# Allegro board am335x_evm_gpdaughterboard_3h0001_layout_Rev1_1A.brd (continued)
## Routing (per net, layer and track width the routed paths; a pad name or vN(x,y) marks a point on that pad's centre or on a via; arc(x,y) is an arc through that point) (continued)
AM335X_XDMA_EVENT_INTR1: length 72.8
  TOP w0.121: v2(104.33,78.13) U43.A15
  LY3 w0.102: 104.59,94.21 104.59,98.21 105.57,99.2 105.57,102.4 104.97,103.01 ; v2(104.33,78.13) 104.33,78.65
  LY3 w0.121: 104.59,94.21 104.59,78.9 104.33,78.65 104.33,78.65 ; 104.97,103.01 104.59,103.39 v1(104.59,118.3)
  LY6 w0.102: 104.09,78.65 104.09,78.37 v2(104.33,78.13)
  LY6 w0.121: v1(110.72,131.95) 111.49,131.19 111.49,119.76 110.03,118.3 v1(104.59,118.3) ; 104.09,78.65 104.09,79.11 v1(103.42,79.79)
  BOTTOM w0.121: v1(110.72,131.95) 110.72,138.66 J3.32 ; R158.2 v1(103.42,79.79)
AUD_BCLK: length 119
  TOP w0.121: v1(106.2,91.97) v1(102.8,91.97) ; v2(104.33,74.12) U43.E15 ; v1(60.74,145.07) 61.16,145.49 U51.38
  LY3 w0.102: v2(104.33,74.12) 104.33,74.54 104.73,74.94 104.73,76.12 105.13,76.52 105.31,76.52 105.94,77.15 105.94,78.52 106.08,78.65
  LY3 w0.121: v1(60.74,145.07) 60.11,144.44 60.11,114.54 v1(60.53,114.12) ; v1(102.8,91.97) 102.8,93.13 102.65,93.28 102.65,98.97 103.03,99.35 103.42,99.35 103.67,99.61 103.67,102.53 103.51,102.68 103.51,109.45 103.21,109.75 v1(103.21,110.19) ; 106.08,78.65 106.2,78.78 v1(106.2,91.97)
  LY6 w0.121: v1(60.53,114.12) 61.68,114.12 62.24,113.56 99.84,113.56 v1(103.21,110.19)
AUD_DIN: length 136.6
  TOP w0.121: v1(62.27,144.06) 62.16,144.16 U51.40 ; v2(104.33,73.12) U43.F15 ; v1(64.99,115.15) 65.16,114.98 98.47,114.98 98.74,114.71 102.15,114.71 105.04,117.6 v1(105.04,118.75)
  LY3 w0.102: v2(104.33,73.12) 104.33,72.71 104.93,72.11 104.93,71.96 105.38,71.52 107.6,71.52 107.86,71.26
  LY3 w0.121: 107.86,71.26 108.02,71.1 110.22,71.1 110.85,71.72 110.85,74.65 111.29,75.09 111.29,82.08 110.58,82.79 110.58,82.81 110.32,83.07 110.32,83.44 110.57,83.69 110.57,107.85 111.01,108.3 111.6,108.3 111.92,108.62 111.92,114.46 109.82,116.55 107.24,116.55 v1(105.04,118.75) ; v1(64.99,115.15) 64.99,134.07 62.16,136.9 62.16,143.95 v1(62.27,144.06)
AUD_DOUT: length 168.9
  TOP w0.121: U51.41 v1(62.66,145.08) ; v2(103.33,73.12) U43.F14
  LY6 w0.102: v2(103.33,73.12) 103.78,73.12 104.17,73.52 104.69,73.52 104.9,73.73 106.5,73.73 106.73,73.96 106.73,74.12 107.13,74.52 107.72,74.52 107.73,74.51 107.73,74.51 107.86,74.51
  LY6 w0.121: 107.86,74.51 108.97,74.51 111.26,76.8 111.26,79.41 113.29,81.44 123.06,81.44 127.44,85.82 127.44,147.87 118.24,157.06 81.44,157.06 77.44,153.06 77.44,152.38 71.22,146.15 63.73,146.15 v1(62.66,145.08)
AUD_FSX: length 112.7
  TOP w0.121: U51.39 v1(61.66,145.1) ; v2(102.33,73.12) U43.F13
  LY3 w0.121: v1(59.85,101.38) 61.18,102.71 61.18,115.29 60.74,115.73 60.74,144.18 v1(61.66,145.1)
  LY6 w0.102: 96.73,78.65 96.73,75.92 96.33,75.52 96.14,75.52 95.94,75.32 95.94,71.93 96.14,71.73 101.53,71.73 101.73,71.93 101.73,72.52 v2(102.33,73.12)
  LY6 w0.121: 96.73,78.65 96.73,78.9 94.09,81.54 94.09,84.49 92.72,85.87 75.66,85.87 74.26,87.26 74.26,92.87 66.33,100.81 60.43,100.81 v1(59.85,101.38)
AUD_HPLOUT: length 31.9
  TOP w0.279: U51.18 v1(63.66,154.21)
  TOP w0.381: C198.1 v1(41.39,145.63)
  BOTTOM w0.381: v1(63.66,154.21) 62.77,155.1 54.14,155.1 50.84,151.8 50.84,147.06 49.25,145.48 41.54,145.48 v1(41.39,145.63)
AUD_HPLOUT_JCK: length 12.8
  TOP w0.381: J26.2 32.52,156.02 34.2,154.34 38.39,154.34 39.92,152.82 C198.2
AUD_HPOUTCABLEDET: length 0.7
  TOP w0.121: v2(103.33,68.13) U43.K14
AUD_HPROUT: length 35.4
  TOP w0.279: v1(61.38,154.22) 61.16,154 U51.23
  TOP w0.381: v1(35.67,145.63) C197.1
  BOTTOM w0.381: v1(61.38,154.22) 61,154.6 54.39,154.6 51.47,151.68 51.47,146.98 49.47,144.97 41.24,144.97 40.73,145.48 36.5,145.48 36.35,145.63 v1(35.67,145.63)
AUD_HPROUT_JCK: length 27.2
  TOP w0.381: C197.2 31.33,148.83 28.74,151.42 28.74,157.64 31.41,160.31 38.39,160.31 39.8,161.72 J26.3
AUD_MCLK: length 82.6
  TOP w0.121: R231.1 v1(75.48,75.52) ; U51.37 60.66,145.88 v1(59.73,144.94) R233.1
  LY3 w0.121: v1(60.74,103.03) 59.73,104.05 v1(59.73,144.94)
  BOTTOM w0.121: v1(75.48,75.52) 71.11,75.52 67.79,78.84 67.79,80.78 67.86,80.84 67.86,83.6 67.35,84.11 67.35,97.7 62.51,102.53 61.24,102.53 v1(60.74,103.03)
AUD_MCLK_CPLD: length 118.2
  TOP w0.121: v1(61.51,144.06) R233.2 ; v1(102.4,115.59) 101.61,116.37 63.96,116.37 63.32,117.02 v1(61.51,117.02) ; v2(105.34,74.12) U43.E16
  LY3 w0.102: 107.86,75.08 107.3,74.52 106.15,74.52 105.75,74.12 v2(105.34,74.12)
  LY3 w0.121: v1(109.82,78.38) 109.82,77.77 108.62,76.57 108.62,75.84 107.86,75.08 ; v1(61.51,117.02) v1(61.51,144.06)
  BOTTOM w0.121: v1(109.82,78.38) 109.82,96.87 110.15,97.19 110.15,108.92 103.47,115.59 v1(102.4,115.59)
AUD_RESETN: length 3.3
  TOP w0.121: R232.1 56.93,149.11 v1(57.54,148.5) 57.56,148.52 U51.33
AUD_VOLUMEDWN: length 151.3
  TOP w0.121: v1(14.69,12.95) SW10.2 SW10.1 12.31,7.2 11.98,7.53 R236.1 ; v2(94.34,63.13) U43.R6
  LY3 w0.121: v1(62.96,69.31) v1(62.96,21.69)
  LY6 w0.102: 88.81,68.54 95.47,68.54 95.73,68.29 95.73,62.93 95.53,62.73 95.15,62.73 94.75,63.13 v2(94.34,63.13)
  LY6 w0.121: 88.81,68.54 73.34,68.54 72.57,69.31 71.34,69.31 71.09,69.57 70.72,69.57 70.47,69.31 v1(62.96,69.31) ; v1(14.69,12.95) 15.13,13.39 51.34,13.39 59.64,21.69 v1(62.96,21.69)
AUD_VOLUMEUP: length 123.7
  TOP w0.121: R235.1 22.14,7.66 22.6,7.2 SW9.1 SW9.2 v1(24.93,12.95) 26.46,14.48 26.46,16.3 28.19,18.03 29.67,18.03 30.37,17.33 30.37,16.49 31.64,15.22 42.53,15.22 48.88,21.57 48.88,24.92 50.15,26.19 57.29,26.19 58.75,27.65 58.75,36.54 62.65,40.44 62.65,44.11 63.66,45.12 v1(91.73,45.12) ; v2(93.34,63.13) U43.R5
  LY3 w0.102: v1(93.28,60.04) 93.28,59.63 93.31,59.6
  LY3 w0.121: v1(91.73,45.12) 93.31,46.7 93.31,59.6
  BOTTOM w0.102: v1(93.28,60.04) 93.28,60.47 92.94,60.81 92.94,62.31 93.34,62.71 v2(93.34,63.13)
AUDIO_BUZZER_TRIG: length 115
  TOP w0.121: R124.2 18.82,120.19 Q9.G 19.93,120.24 21.07,121.38 v1(26.75,121.38) ; v2(92.34,67.13) U43.L4
  LY6 w0.102: 88.81,66.6 91.81,66.6 v2(92.34,67.13)
  LY6 w0.121: v1(66.06,67.87) 67.85,66.08 84.7,66.08 85.23,66.6 88.81,66.6
  BOTTOM w0.121: v1(26.75,121.38) 26.75,119.22 33.1,112.87 46.57,112.87 52.92,106.52 52.92,95.44 62.3,86.06 62.3,84.89 64.72,82.47 64.72,79.78 66.06,78.43 v1(66.06,67.87)
BUZZER_N: length 5.3
  TOP w0.381: SPKR1.2 20.87,125.56 Q9.D
BUZZER_P: length 5.5
  TOP w0.381: SPKR1.1 27.22,123.35 27.85,122.72 R120.1
CAN0_H: length 14
  TOP w0.121: J11.7 165.44,141.94 165.14,141.64 160.18,141.64 159.74,141.19 U17.1 158.01,140.37 155.74,140.37 155.55,140.56 U16.7
CAN0_L: length 14.7
  TOP w0.121: U16.6 156.69,140.12 158.01,140.12 U17.2 159.8,140.27 159.8,140.88 160.31,141.39 164.88,141.39 165.71,140.56 J11.2
CAN0_RXD: length 101.8
  TOP w0.102: 107.86,69.68 107.2,69.02 104.44,69.02 U43.J15
  TOP w0.121: 107.86,69.68 107.94,69.76 109,69.76 109.6,70.35 110.13,70.35 110.3,70.52 115.1,70.52 115.11,70.53 120.81,70.53 v1(121.7,69.63) ; v1(142.79,141.52) R43.1 C57.1
  BOTTOM w0.121: v1(121.7,69.63) 130.59,78.52 130.59,129.32 v1(142.79,141.52)
CAN0_RXDF: length 3.2
  TOP w0.121: R43.2 U16.2
CAN0_TXD: length 100.5
  TOP w0.102: 107.86,70.01 107.78,70.01 107,69.23 105.67,69.23 105.28,69.63 U43.J16
  TOP w0.121: R44.1 v1(142.79,138.98) ; v1(122.47,69.63) 121.32,70.78 110.2,70.78 110.03,70.6 109.46,70.6 108.88,70.01 107.86,70.01
  BOTTOM w0.121: v1(122.47,69.63) 127.67,69.63 132.12,74.08 132.12,128.31 v1(142.79,138.98)
CAN0_TXDF: length 4.5
  TOP w0.121: U16.3 R44.2 C58.1
CPLD_CFG0: length 101
  TOP w0.121: v1(112.29,68.76) 112.29,52.08 106.74,46.53 85.62,46.53 81.83,50.33 55.66,50.33 55.28,49.95 R151.2 SW8.1 ; v2(99.34,64.13) U43.P10
  LY6 w0.102: v2(99.34,64.13) 98.87,64.59 98.87,67.22 99.17,67.52 99.29,67.52 99.73,67.96 99.73,68.08 100.7,69.05 107.9,69.05 107.91,69.06
  LY6 w0.121: v1(112.29,68.76) 111.85,68.76 111.42,68.33 110.22,68.33 109.83,68.72 108.5,68.72 108.16,69.06 107.91,69.06
CPLD_CFG1: length 74.1
  TOP w0.121: SW8.2 R150.2 56.03,52.73 82.04,52.73 v1(85.32,49.46) ; v2(95.34,63.13) U43.R7
  LY3 w0.102: v2(95.34,63.13) 95.73,63.52 96.5,63.52 96.73,63.29 96.73,60.88 95.45,59.6
  LY3 w0.121: 95.45,59.6 94.53,58.68 94.53,45.01 90.59,41.08 v1(89.56,41.08)
  BOTTOM w0.121: v1(85.32,49.46) 89.56,45.22 v1(89.56,41.08)
CPLD_CFG2: length 52.8
  TOP w0.121: v2(96.34,63.13) U43.R8 ; v1(90.72,55.16) 89.83,54.27 63.28,54.27 62.46,55.09 55.85,55.09 R149.2 SW8.3
  LY3 w0.102: v2(96.34,63.13) 95.73,62.52 95.73,61.92 95.53,61.72 93.33,61.72 92.93,61.33 92.93,60.54 92.74,60.35 92.74,59.6
  LY3 w0.121: v1(90.72,55.16) 90.72,57.06 92.74,59.09 92.74,59.6
CPLD_CFG3: length 63.4
  TOP w0.121: v2(97.34,63.13) U43.R9 ; v1(88.3,55.6) 86.08,57.81 56.03,57.81 R148.2 SW8.4
  LY3 w0.102: 98.18,59.6 98.18,65.21 97.67,65.72 96.34,65.72 95.94,65.33 95.94,64.92 96.14,64.72 96.31,64.72 96.94,64.09 96.94,63.96 97.34,63.57 v2(97.34,63.13)
  LY3 w0.121: v1(97.14,55.6) 97.14,57.3 98.18,58.35 98.18,59.6
  LY6 w0.121: v1(88.3,55.6) 88.74,55.6 88.74,55.6 96.7,55.6 v1(97.14,55.6)
CPLD_CLK12MHZ: length 25
  TOP w0.121: v2(94.34,70.13) U43.J6 ; R230.1 v1(76.75,75.48)
  LY3 w0.121: v1(78.52,69) 76.75,70.78 v1(76.75,75.48)
  LY6 w0.102: v2(94.34,70.13) 93.21,69 88.81,69
  LY6 w0.121: v1(78.52,69) 88.81,69
CPLD_CLK25MHZ: length 17.4
  TOP w0.121: v2(94.34,68.13) U43.K6 ; R157.1 v1(79.21,66.59)
  LY3 w0.102: v2(94.34,68.13) 93.91,68.13 93.38,67.6 88.81,67.6
  LY3 w0.121: v1(79.21,66.59) 80.22,67.6 88.81,67.6
CPLD_CLKSA: length 61.4
  TOP w0.121: v2(102.33,68.13) U43.K13
  LY3 w0.121: v1(121.7,66.72) 121.26,67.16 121.26,70.07 122.02,70.83 v1(122.02,84.54)
  LY6 w0.102: 108.01,68.81 103.02,68.81 v2(102.33,68.13)
  LY6 w0.121: v1(121.7,66.72) 121.7,67.46 120.24,68.92 116.58,68.92 115.67,68.02 109.93,68.02 109.62,68.33 108.5,68.33 108.01,68.81 ; v1(122.02,84.54) 121.6,84.96 110.36,84.96 107.98,82.59 v1(103.42,82.59)
  BOTTOM w0.121: R158.1 v1(103.42,82.59)
CPLD_CLRN: length 10.2
  TOP w0.102: 98.62,59.6 98.62,60.28 98.44,60.46 98.44,65.23 U43.N10
  TOP w0.121: 98.62,59.6 99.23,58.99 99.29,58.99 99.61,58.68 R156.1
CPLD_DEVOE: length 13.2
  TOP w0.121: v1(95.8,55.16) 95.8,54.52 TP32.1 ; v2(97.34,65.13) U43.N9
  LY3 w0.102: v2(97.34,65.13) 97.34,64.71 97.73,64.31 97.73,60.18 97.15,59.6
  LY3 w0.121: v1(95.8,55.16) 96.26,55.62 96.26,58.71 97.15,59.6
CPLD_GCLK3: length 26.8
  TOP w0.121: v2(102.33,70.13) U43.J13 ; TP33.1 v1(120.49,72.3)
  LY3 w0.121: v1(120.49,72.3) v1(120.49,69.57)
  LY6 w0.102: 107.86,69.31 107.81,69.26 103.2,69.26 v2(102.33,70.13)
  LY6 w0.121: 107.86,69.31 108.24,69.69 109.84,69.69 110.22,69.32 110.58,69.32 110.69,69.43 119.91,69.43 120.05,69.57 v1(120.49,69.57)
CPLD_TCK: length 67
  TOP w0.121: v1(42.33,77.51) R159.2 J22.1 ; v2(92.34,63.13) U43.R4
  LY3 w0.121: v1(42.33,77.51) R159.2 41.44,75.86 41.44,69.51 v1(42.07,68.87)
  LY6 w0.102: v2(92.34,63.13) 91.8,63.66 88.81,63.66
  LY6 w0.121: v1(42.07,68.87) 43.35,68.87 44.37,67.86 57.82,67.86 58.52,67.16 65.12,67.16 66.97,65.32 74.84,65.32 76.3,63.85 83.42,63.85 83.6,63.66 88.81,63.66
CPLD_TDI: length 59.1
  TOP w0.121: R153.1 v1(43.73,66.59) J22.9 45.95,64.95 46.32,64.58 54.88,64.58 58.43,61.02 76.06,61.02 v1(77.43,62.39) ; v2(95.34,66.13) U43.M7
  LY3 w0.102: v2(95.34,66.13) 94.88,66.59 88.81,66.59
  LY3 w0.121: v1(77.43,62.39) 80.61,65.57 84.31,65.57 85.35,66.6 88.79,66.6 88.81,66.59
CPLD_TDO: length 83.4
  TOP w0.121: v2(94.34,65.13) U43.N6 ; R154.1 v1(43.73,74.21) J22.3 ; v1(81.19,61.82) 82.07,60.94 v1(85.47,60.94)
  LY3 w0.121: v1(43.73,74.21) 47.09,70.84 47.09,52.17 47.02,52.11 v1(47.02,51.98)
  BOTTOM w0.102: 88.81,61.56 91.53,61.56 91.86,61.89 91.86,63.41 92.11,63.66 93.51,63.66 93.73,63.88 93.73,64.52 v2(94.34,65.13)
  BOTTOM w0.121: v1(81.19,61.82) 81.19,61.12 72.73,52.67 53.3,52.67 52.3,51.67 47.33,51.67 v1(47.02,51.98) ; 88.81,61.56 88.03,61.56 87.41,60.94 v1(85.47,60.94)
CPLD_TMS: length 64.1
  TOP w0.121: v1(42.07,68.11) 42.71,68.74 42.71,70.01 42.33,70.4 R155.1 J22.5 ; v2(93.34,64.13) U43.P5
  LY6 w0.102: v2(93.34,64.13) 93.34,63.71 93.73,63.31 93.73,62.93 93.53,62.73 89.17,62.73 89.13,62.78 87.86,62.78
  LY6 w0.121: v1(42.07,68.11) 42.65,67.54 57.57,67.54 58.27,66.84 64.55,66.84 67.79,63.6 79.73,63.6 80.49,62.84 81.01,62.84 81.64,63.47 83.27,63.47 83.96,62.78 87.86,62.78
EXP3_P9: length 3.8
  TOP w0.121: TP3.1 v1(92.62,122.85)
  BOTTOM w0.121: J4.9 v1(92.62,122.85)
EXP_PB_POWERON: length 8.9
  LY3 w0.121: J2.12 47.65,108.38 TP1.1
F_TSC_CLK: length 63.2
  TOP w0.121: v2(106.34,73.12) U43.F17
  LY3 w0.102: 107.51,73.88 106.75,73.12 v2(106.34,73.12)
  LY3 w0.121: v1(111.43,110.19) 110.32,109.09 110.32,83.79 110.07,83.54 110.07,82.97 110.35,82.69 110.35,80.8 110.7,80.45 110.7,76.68 107.91,73.88 107.51,73.88
  BOTTOM w0.121: 101.89,121.45 101.89,122.3 111.11,122.3 111.43,121.98 v1(111.43,110.19)
F_TSC_GIO0: length 62.1
  TOP w0.121: v2(107.34,73.12) U43.F18
  LY6 w0.102: 107.86,73 107.46,73 v2(107.34,73.12)
  LY6 w0.121: 107.86,73 109.83,73 113.32,76.49 113.32,78.24 v1(114.15,79.07)
  BOTTOM w0.121: 99.35,121.45 98.71,120.8 98.71,119.65 101.31,117.05 103.72,117.05 110.4,110.37 110.4,97.07 110.07,96.74 110.07,82.69 113.69,79.07 v1(114.15,79.07)
F_TSC_GIO1: length 57.2
  TOP w0.121: v2(101.34,72.13) U43.G12
  LY6 w0.102: 98.94,78.65 98.94,78.62 98.7,78.39 98.7,74.18 99.15,73.73 100.34,73.73 100.92,73.16 100.92,72.54 v2(101.34,72.13)
  LY6 w0.121: 98.94,78.65 98.94,81.16 99.34,81.56 v1(99.34,81.63)
  BOTTOM w0.102: 97.45,94.21 97.45,94.46 97.26,94.65 97.26,103.01
  BOTTOM w0.121: 97.26,103.01 97.26,120.51 99.29,122.54 100.37,122.54 100.62,122.29 100.62,121.45 ; v1(99.34,81.63) 97.45,83.52 97.45,94.21
F_TSC_GIO2: length 63.6
  TOP w0.121: v2(102.33,72.13) U43.G13
  LY6 w0.102: 107.86,73.57 107.23,73.57 107.17,73.52 107.17,73.52 106.94,73.29 106.94,72.91 106.76,72.72 106.04,72.72 105.84,72.52 105.17,72.52 104.94,72.29 104.94,72.05 104.62,71.73 103.15,71.73 102.75,72.13 v2(102.33,72.13)
  LY6 w0.121: v1(114.15,80.75) 112.96,80.75 111.57,79.36 111.57,76.53 109.28,74.24 108.75,74.24 108.08,73.57 107.86,73.57
  BOTTOM w0.121: v1(114.15,80.75) 112.61,80.75 110.32,83.04 110.32,96.6 110.65,96.94 110.65,110.86 103.16,118.35 J21.8
F_TSC_RSV0: length 66.5
  TOP w0.121: v2(105.34,73.12) U43.F16
  LY3 w0.102: 107.55,74.36 107.53,74.36 106.89,73.72 105.93,73.72 v2(105.34,73.12)
  LY3 w0.121: 107.55,74.36 109.05,75.86 109.05,76.47 110.33,77.74 110.33,80.2 110.07,80.46 110.07,82.62 109.82,82.87 109.82,83.64 110.07,83.89 110.07,115.67 v1(109.63,116.11)
  LY6 w0.121: v1(109.63,116.11) 102.26,116.11 98.64,119.73 98.64,121.9 99.04,122.3 102.31,122.3 103.16,121.45
GP_I2C_SCL: length 157.3
  TOP w0.121: v1(66.08,85.64) 65.19,85.64 65.11,85.56 U10.8 ; U9.4 61.39,92.76 v1(61,92.37) 61,91.49 58.84,89.33 v1(52.48,89.33) U12.3 ; U39.14 v1(54.82,45.14) ; U51.1 67.94,147.02 v1(68.36,146.6) ; v1(63.09,97.32) U13.2 ; U11.8 65.72,80.01 65.95,80.23 v1(65.95,81.19) ; U40.14 v1(54.82,34.98)
  LY3 w0.121: v1(49.95,47.24) 49.95,86.81 v1(52.48,89.33) ; v1(68.36,146.6) 68.36,139.36 67.04,138.03 67.04,99.16 65.64,97.76 63.53,97.76 v1(63.09,97.32) ; v1(54.82,45.14) 52.3,42.63 v1(52.3,36.11)
  LY6 w0.121: v1(54.82,34.98) 53.68,36.11 v1(52.3,36.11)
  BOTTOM w0.121: 65.51,85.64 65.51,81.63 v1(65.95,81.19) ; 65.51,85.64 64.38,85.64 63.04,86.97 63.04,88.99 61,91.03 v1(61,92.37) 60.56,92.81 60.56,95.29 62.59,97.32 v1(63.09,97.32) ; 65.51,85.64 v1(66.08,85.64) ; v1(54.82,45.14) 52.71,47.24 v1(49.95,47.24)
GP_I2C_SDA: length 150.1
  TOP w0.121: v1(63.66,90.08) 62.91,90.83 U9.6 ; v1(60.87,81.19) 61.63,81.19 61.84,80.99 U11.1 ; U39.15 v1(54.17,42.83) 54.17,42.32 v1(54.86,42.32) ; U13.1 61.82,98.78 v1(61.76,98.72) ; v1(60.74,85.64) R24.1 61.71,85.56 U10.1 ; v1(59.67,90.83) v1(52.48,90.83) U12.4 ; U40.15 v1(54.17,32.67) ; U51.2 v1(67.82,147.52)
  LY3 w0.121: v1(54.86,42.32) 54.86,38.76 54.17,38.07 v1(54.17,32.67) ; 59.99,85.64 v1(60.74,85.64) ; 59.99,85.64 59.67,85.96 v1(59.67,90.83) 59.67,96.62 v1(61.76,98.72) 63.54,100.49 63.54,105.57 65.57,107.61 65.57,138.21 67.82,140.46 v1(67.82,147.52) ; 59.99,85.64 59.99,82.07 v1(60.87,81.19) 60.87,79.91 61.06,79.72 61.06,65.28 60.24,64.46 v1(60.24,41.88)
  LY6 w0.121: v1(63.66,90.08) 60.42,90.08 v1(59.67,90.83)
  BOTTOM w0.121: v1(54.86,42.32) 55.42,41.77 59.07,41.77 59.19,41.88 v1(60.24,41.88)
GPMC_AD0: length 104.9
  TOP w0.121: U6.47 v1(91.74,89) ; v2(91.33,72.13) U43.G3 ; U7.47 v1(91.74,101.76) ; v1(97.19,146.72) 96.43,147.48 94.14,147.48 94.01,147.35 U23.14
  LY3 w0.121: 92.43,101.76 v1(91.74,101.76) ; 92.43,101.76 92.89,101.3 92.89,91.66 91.74,90.51 v1(91.74,89) 91.74,87.83 91.43,87.52 91.43,85.31 v1(90.97,84.85) ; 92.43,101.76 92.43,104.34 92.89,104.8 92.89,112.53 86.59,118.83 v1(86.59,134.58)
  LY6 w0.102: 93.97,78.65 93.97,78.52 93.94,78.52 93.94,77.92 94.34,77.52 94.53,77.52 94.73,77.32 94.73,76.92 94.33,76.52 94.14,76.52 93.94,76.32 93.94,75.96 94.38,75.52 95.53,75.52 95.73,75.32 95.73,71.93 95.53,71.73 92.15,71.73 91.75,72.13 v2(91.33,72.13)
  LY6 w0.121: v1(90.97,84.85) 91.51,84.31 91.51,81.55 93.21,79.84 93.27,79.84 93.97,79.14 93.97,78.65
  BOTTOM w0.121: v1(97.19,146.72) 97.19,145.95 97.51,145.63 97.51,136.78 95.86,135.13 87.14,135.13 v1(86.59,134.58)
GPMC_AD1: length 108.9
  TOP w0.121: v1(94.28,91.54) 91.89,91.54 91.78,91.65 v1(91.34,91.65) U6.46 ; U7.46 v1(91.34,104.35) ; U23.15 93.51,147.23 94.02,147.74 96.94,147.74 v1(97.19,147.99) ; v2(90.33,72.13) U43.G2
  LY3 w0.102: 88.81,72.53 89.51,72.53 89.92,72.13 v2(90.33,72.13)
  LY3 w0.121: v1(88.37,134.58) 88.37,131.94 89.19,131.11 90.13,131.11 91.21,130.03 91.21,120.06 92.37,118.91 94.47,118.91 94.72,118.66 94.72,115.76 94.33,115.37 94.33,110.46 94.53,110.27 v1(94.53,104.69) ; v1(86.88,78.11) 86.88,78.07 85.61,76.8 85.61,75.17 88.25,72.53 88.81,72.53
  LY6 w0.121: v1(94.53,104.69) 94.19,104.35 v1(91.34,104.35)
  BOTTOM w0.121: v1(97.19,147.99) 97.75,147.43 97.75,136.62 95.72,134.58 v1(88.37,134.58) ; v1(94.53,104.69) 94.02,104.18 94.02,102.27 93.84,102.09 93.84,96.24 94.28,95.8 v1(94.28,91.54) ; v1(86.88,78.11) 86.88,78.6 87.92,79.64 87.92,85.25 90.49,87.83 90.49,90.8 v1(91.34,91.65)
GPMC_AD2: length 92.4
  TOP w0.121: v1(97.07,144.44) 96.57,143.94 U23.8 ; v1(91.35,105.32) 90.54,104.51 U7.44 ; v1(91.35,92.62) 90.54,91.81 U6.44 ; v2(89.34,72.13) U43.G1
  LY3 w0.102: v2(89.34,72.13) 88.81,72.13
  LY3 w0.121: v1(85.83,71.35) 86,71.52 86,71.54 86.59,72.13 88.81,72.13
  LY6 w0.121: v1(97.07,144.44) 97.07,142.31 95.33,140.58 95.33,134.47 93.88,133.01 93.88,122.05 v1(92.27,120.44)
  BOTTOM w0.121: 92.18,92.62 92.18,88.75 90.59,87.17 90.47,87.17 88.23,84.93 88.23,77.9 87.07,76.74 86.92,76.74 85.83,75.66 v1(85.83,71.35) ; 92.18,92.62 v1(91.35,92.62) ; 92.18,92.62 92.89,93.33 92.89,100.39 92.43,100.85 92.43,105.32 ; v1(92.27,120.44) 92.27,116.92 92.89,116.3 92.89,105.78 92.43,105.32 ; 92.43,105.32 v1(91.35,105.32)
GPMC_AD3: length 92.5
  TOP w0.121: v1(97.07,145.45) 96.55,144.94 U23.10 ; U6.43 90.14,88.87 89.45,88.18 v1(89.45,88.05) ; U7.43 v1(90.14,101.76) ; v2(94.34,73.12) U43.F6
  LY6 w0.102: v2(94.34,73.12) 93.94,73.52 93.94,74.63 93.73,74.84 93.73,75.29 93.5,75.52 90.44,75.52 90.23,75.73 90.17,75.73 89.83,76.08 89.83,76.35 89.44,76.73 88.82,76.73 88.81,76.75
  LY6 w0.121: v1(97.07,145.45) 96.61,145 96.61,142.52 95.02,140.93 95.02,135.7 93.57,134.25 93.57,122.62 v1(91.83,120.88) ; v1(86.89,77.19) 87.33,76.75 88.81,76.75
  BOTTOM w0.121: v1(91.83,120.88) 91.83,114.26 92.58,113.51 92.58,107.21 90.27,104.9 90.27,102.34 90.14,102.21 v1(90.14,101.76) 89.41,101.04 89.41,100.55 87.99,99.13 87.99,95.03 88.81,94.2 89.17,94.2 90.21,93.16 90.21,92.23 90.24,92.19 90.24,91.78 90.21,91.74 90.21,88.81 v1(89.45,88.05) 89.45,87.13 87.63,85.31 87.63,79.91 86.4,78.68 86.4,77.66 86.87,77.19 v1(86.89,77.19)
GPMC_AD4: length 103.3
  TOP w0.121: U6.41 v1(89.34,89.14) ; 84.62,143.55 v1(84.62,142.79) ; U7.41 89.34,101.49 v1(90.08,100.75) 89.26,99.93 v1(86.71,99.93) ; v2(93.34,73.12) U43.F5
  LY3 w0.102: v2(93.34,73.12) 92.73,73.73 92.73,75.29 92.5,75.52 92.07,75.52 91.74,75.85 91.74,76.36 91.58,76.52 90.18,76.52 89.94,76.76 89.94,78.64 89.95,78.65
  LY3 w0.121: v1(83.35,114.25) 82.5,113.4 82.5,107.77 83.51,106.76 88.04,106.76 89.24,105.55 89.24,101.58 v1(90.08,100.75) 89.24,99.91 89.24,97.3 88.5,96.55 88.5,93.54 89.21,92.82 89.21,89.71 89.34,89.58 v1(89.34,89.14) ; v1(84.62,142.79) 84.62,141.84 84.69,141.77 84.69,133.88 83.35,132.53 v1(83.35,129.13) ; v1(86.01,84.77) 86.01,84.37 88.18,82.21 89.04,82.21 89.06,82.22 89.55,82.22 89.95,81.83 89.95,81.32 90.61,80.66 90.61,79.44 89.95,78.78 89.95,78.65
  BOTTOM w0.121: v1(83.35,129.13) 83.6,128.88 83.6,124.37 83.35,124.11 v1(83.35,114.25) ; v1(86.71,99.93) 86.09,99.31 86.09,97.26 86.08,97.25 86.08,89.32 86.09,89.31 86.09,88.68 86.08,88.67 86.08,85.76 86.01,85.69 v1(86.01,84.77)
GPMC_AD5: length 101.6
  TOP w0.121: v2(92.34,73.12) U43.F4 ; U7.40 88.94,104.69 v1(89.7,105.45) ; U6.40 88.94,91.99 v1(89.7,92.75) 89.26,92.75 89.07,92.93 83.42,92.93 81.76,91.28 81.76,90 v1(82.63,89.14) ; R257.1 v1(86.4,142.91)
  LY3 w0.121: v1(86.4,142.91) 87.29,142.02 87.29,136.15 86.15,135.01 86.15,117.35 92.58,110.91 92.58,106.93 92.09,106.44 90.69,106.44 v1(89.7,105.45) 90.18,104.96 90.18,104.15 89.7,103.67 89.7,101.53 90.02,101.21 91.95,101.21 92.58,100.57 92.58,94.51 91.76,93.68 90.64,93.68 v1(89.7,92.75) ; v1(83.07,78.87) 85.18,76.76 85.18,74.92 86.27,73.82 v1(86.27,73.76)
  LY6 w0.102: v2(92.34,73.12) 91.73,73.73 88.84,73.73 88.81,73.76
  LY6 w0.121: v1(86.27,73.76) 88.81,73.76
  BOTTOM w0.121: v1(83.07,78.87) 83.07,84.32 82.63,84.76 v1(82.63,89.14)
GPMC_AD6: length 112.4
  TOP w0.121: U7.38 v1(88.14,104.35) ; U6.38 v1(88.14,91.65) ; R256.1 v1(78.9,143.04) ; v2(91.33,73.12) U43.F3
  LY3 w0.102: v2(91.33,73.12) 90.92,73.12 90.51,73.53 88.81,73.53
  LY3 w0.121: v1(85.19,129.55) 85.19,141.45 85.31,141.57 85.31,143.59 84.59,144.3 80.17,144.3 v1(78.9,143.04) ; 83.11,87.36 v1(83.11,85.38) ; 83.11,87.36 81.76,88.71 81.76,104.17 83.61,106.02 88.01,106.02 88.58,105.44 88.58,104.79 v1(88.14,104.35) ; 83.11,87.36 86.87,87.36 87.69,88.18 87.69,91.2 v1(88.14,91.65) ; v1(84.37,78.8) 87.01,78.8 87.76,78.05 87.76,74.05 88.28,73.53 88.81,73.53
  BOTTOM w0.121: v1(84.37,78.8) 84.37,84.24 83.22,85.38 v1(83.11,85.38) ; v1(85.19,129.55) 85.67,129.55 86.14,129.07 86.14,125.01 84.1,122.96 84.1,112.45 82.5,110.85 82.5,107.72 83.71,106.51 86.33,106.51 87.48,105.37 87.48,105.01 v1(88.14,104.35)
GPMC_AD7: length 93.3
  TOP w0.121: v1(81.32,143.04) 81.32,143.05 80.82,143.55 R258.1 ; U7.37 87.74,101.56 v1(88.56,100.75) ; v1(88.56,88.05) 88.56,88.18 87.74,88.99 U6.37 ; v2(90.33,73.12) U43.F2
  LY3 w0.102: v2(90.33,73.12) 89.89,73.12 89.79,73.02 88.81,73.02
  LY3 w0.121: v1(81.32,143.04) 82.33,144.06 84.49,144.06 85.06,143.49 85.06,141.7 84.94,141.58 84.94,131.92 84.03,131.02 84.03,124.9 82.19,123.05 82.19,107.72 83.46,106.45 87.97,106.45 88.98,105.43 88.98,101.58 88.56,101.16 v1(88.56,100.75) ; 88.81,73.02 88.35,73.02 87.08,74.29 87.08,75.86 v1(86.19,76.75)
  BOTTOM w0.121: v1(86.19,76.75) 86.15,76.79 86.15,79.34 87.38,80.57 87.38,86.87 v1(88.56,88.05) 87.61,89 87.61,99.8 v1(88.56,100.75)
GPMC_AD8: length 18.1
  TOP w0.121: U7.36 87.34,104.61 v1(88.05,105.32) ; U6.36 87.34,91.79 v1(88.05,92.49)
  LY3 w0.121: v1(88.05,92.49) 88.05,98.22 87.99,98.28 87.99,98.64 88.05,98.71 88.05,103.54 87.67,103.92 87.67,104.94 v1(88.05,105.32)
GPMC_AD9: length 15.9
  TOP w0.121: U6.35 v1(86.94,89) ; U7.35 v1(86.94,101.76)
  LY3 w0.121: v1(86.94,89) 86.96,89 87.38,89.41 87.38,101.32 v1(86.94,101.76)
GPMC_AD10: length 19
  TOP w0.121: v1(86.91,88.05) 86.14,88.81 U6.33 ; v1(86.91,100.75) 86.14,101.51 U7.33
  LY3 w0.121: v1(86.91,88.05) 86.5,88.45 86.5,89.29 86.98,89.78 86.98,95.04 86.27,95.75 86.27,100.11 v1(86.91,100.75)
GPMC_AD11: length 18.2
  TOP w0.121: v1(86.52,105.32) 85.74,104.54 U7.32 ; v1(86.52,92.49) 85.74,91.71 U6.32
  LY3 w0.121: v1(86.52,92.49) 86.52,93.13 86.02,93.64 86.02,104.81 v1(86.52,105.32)
GPMC_AD12: length 18.1
  TOP w0.121: U6.30 v1(84.94,92.49) ; U7.30 84.94,104.65 85.04,104.75 v1(85.04,105.38)
  LY3 w0.121: v1(84.94,92.49) 85.44,92.99 85.44,96.85 84.81,97.48 84.81,98.64 85,98.83 85,101.42 84.75,101.67 84.75,104.39 85.04,104.69 v1(85.04,105.38)
GPMC_AD13: length 18.8
  TOP w0.121: U7.29 v1(84.54,101.26) ; U6.29 84.54,88.86 v1(83.73,88.05)
  LY3 w0.121: v1(84.54,101.26) 84.54,95.97 83.7,95.13 83.7,92.92 84.58,92.04 84.58,88.9 v1(83.73,88.05)
GPMC_AD14: length 15.9
  TOP w0.121: U7.27 v1(83.74,101.77) ; U6.27 v1(83.74,89)
  LY3 w0.121: v1(83.74,89) 83.74,89.62 83.48,89.89 83.48,92.8 83.45,92.82 83.45,95.05 83.3,95.2 83.3,97.99 83.74,98.43 v1(83.74,101.77)
GPMC_AD15: length 17.5
  TOP w0.121: v1(82.97,91.86) 83.34,91.49 U6.26 ; U7.26 v1(83.34,105.07)
  LY3 w0.121: v1(83.34,105.07) 83.34,102.02 82.5,101.18 82.5,97.85 82.27,97.63 82.27,94.2 82.97,93.51 v1(82.97,91.86)
GPMC_CS1N: length 116.4
  TOP w0.121: v2(93.34,72.13) U43.G5 ; v1(96.18,146.67) 95.87,146.98 94.82,146.98 U23.13
  LY3 w0.121: v1(76.38,133.9) 76.38,108.06 76.76,107.68 76.76,97.94 78.07,96.64 78.07,88.86 78.26,88.66 78.26,82.62 79.01,81.87 79.01,73.72 v1(79.03,73.7)
  LY6 w0.102: v2(93.34,72.13) 93.3,72.13 92.9,72.53 89.9,72.53 89.11,73.32 88.81,73.32
  LY6 w0.121: 88.81,73.32 83.85,73.32 83.48,73.7 v1(79.03,73.7)
  BOTTOM w0.121: v1(76.38,133.9) 95.4,133.9 98,136.5 98,147.99 97.56,148.43 97,148.43 96.18,147.61 v1(96.18,146.67)
GPMC_CS2N: length 98.6
  TOP w0.121: v2(92.34,72.13) U43.G4 ; v1(95.29,146.47) 95.23,146.41 U23.12
  LY3 w0.102: v2(92.34,72.13) 91.92,72.13 91.51,71.72 88.81,71.72
  LY3 w0.121: v1(86.44,71.35) 86.54,71.35 86.91,71.72 87.23,71.72 87.23,71.73 87.6,71.73 87.6,71.72 88.81,71.72 ; v1(86.94,84.82) 87.08,84.82 87.66,84.24 90.51,84.24 91.8,84.24 92.2,84.64 92.2,86.26 93.32,87.37 93.32,103.37 93.14,103.54 93.14,114.96 88.74,119.37 88.74,129.1 87.68,130.15 87.68,139.86 90.54,142.72 93.82,142.72 95.29,144.18 v1(95.29,146.47)
  BOTTOM w0.121: v1(86.44,71.35) 86.44,71.17 86.18,70.91 85.64,70.91 85.39,71.17 85.39,82.96 86.28,83.85 86.28,83.85 86.94,84.51 v1(86.94,84.82)
HAPT_N: length 6.5
  TOP w0.381: U41.2 156.68,19.47 159.68,19.47 160.82,18.33 Q10.D
HAPT_P: length 4
  TOP w0.381: C129.1 R125.1 158.41,16.93 158.16,17.17 U41.1
HAPTICS_TRIG: length 99.4
  TOP w0.121: v1(112.56,69.87) 113.72,69.87 114.21,69.38 114.21,65.95 113.64,65.38 113.64,55.22 141.59,27.27 159.24,27.27 165.59,20.92 v1(165.59,17.39) Q10.G 164.74,16.28 R128.2 ; v2(104.33,67.13) U43.L15
  LY3 w0.102: 107.86,69.25 105.87,69.25 104.33,67.72 v2(104.33,67.13)
  LY3 w0.121: v1(112.56,69.87) 112.12,69.43 111.56,69.43 111.49,69.51 111.04,69.51 110.78,69.25 110.26,69.25 109.82,69.69 108.44,69.69 108,69.25 107.86,69.25
IDMEM_WP: length 2.7
  TOP w0.121: R1.1 U1.7
IOEXPAND0_D0: length 30.7
  TOP w0.121: U39.4 v1(55.47,39.54)
  BOTTOM w0.121: J18.2 45.12,22.01 45.12,39.03 46.08,39.98 55.02,39.98 v1(55.47,39.54)
IOEXPAND0_D1: length 20.2
  TOP w0.121: U39.5 v1(56.12,37.23)
  BOTTOM w0.121: v1(56.12,37.23) 54.56,35.67 52.56,35.67 49.2,32.3 49.2,26.34 J18.4
IOEXPAND0_D2: length 20.1
  TOP w0.121: U39.6 v1(56.77,39.54)
  BOTTOM w0.121: J18.6 48.45,28.13 48.45,32.91 53.22,37.67 54.9,37.67 v1(56.77,39.54)
IOEXPAND0_D3: length 20.7
  TOP w0.121: U39.7 v1(57.41,37.23)
  LY6 w0.121: J18.8 55.2,28.49 58.51,31.79 58.51,36.14 v1(57.41,37.23)
IOEXPAND0_D4: length 48.5
  TOP w0.121: U39.9 v1(58.07,42.83) 55.22,39.98 45.7,39.98 44.87,39.15 44.87,38.14 44.23,37.5 43.09,37.5 42.58,37 42.58,35.09 42.84,34.84 44.11,34.84 44.49,34.45 45.38,34.45 J18.12 44.87,32.17 43.09,32.17 42.58,31.66 42.58,22.17 37.79,17.39 Q1.G 37.25,16.89 R112.2
IOEXPAND0_D5: length 56.5
  TOP w0.121: R114.2 v1(32.8,16.64) 32.8,16.89 Q2.G ; U39.10 v1(57.41,45.14) 58.19,45.14 58.51,44.82 58.51,37.58 57.49,36.57 47.61,36.57 47.15,36.11 J18.14
  LY3 w0.121: J18.14 47.46,34.91 47.46,20.69 43.91,17.14 33.3,17.14 v1(32.8,16.64)
IOEXPAND0_D6: length 51.6
  TOP w0.121: U39.11 v1(56.77,42.83) ; v1(29.68,17.39) Q3.G 28.36,16.89 R115.2
  LY3 w0.121: v1(29.68,17.39) 42.01,17.39 45.25,20.62 45.25,37.63 J18.16
  LY6 w0.121: J18.16 47.85,40.23 54.61,40.23 56.77,42.39 v1(56.77,42.83)
IOEXPAND0_D7: length 57.8
  TOP w0.121: J18.18 50.66,45.58 55.67,45.58 v1(56.12,45.14) U39.12 ; 23.91,15.79 23.91,16.89 Q4.G v1(25.26,17.39)
  LY3 w0.121: v1(25.26,17.39) 25.7,17.83 42.08,17.83 44.94,20.68 44.94,39.86 J18.18
IOEXPAND0_INTN: length 61.4
  TOP w0.121: U39.13 v1(55.47,42.83) ; v2(92.34,64.13) U43.P4
  LY3 w0.102: 88.81,64.52 91.5,64.52 91.89,64.13 v2(92.34,64.13)
  LY3 w0.121: v1(78.95,49.01) 78.95,56.58 86.9,64.52 88.81,64.52
  BOTTOM w0.121: v1(78.95,49.01) 79.77,49.01 80.4,49.64 80.93,49.64 81.18,49.39 81.18,47.86 74.83,41.51 64.66,41.51 63.84,42.32 58.94,42.32 58.7,42.08 55.78,42.08 55.47,42.39 v1(55.47,42.83) 55.03,43.27 R100.1
IOEXPAND1_D0: length 19.8
  TOP w0.121: U40.4 v1(55.47,29.38)
  BOTTOM w0.121: v1(55.47,29.38) 55.47,25.36 51.02,20.92 49.08,20.92 47.83,19.67 44.92,19.67 J18.1
IOEXPAND1_D1: length 15.1
  TOP w0.121: U40.5 v1(56.12,27.07) 55.61,26.56 48.55,26.56 46.77,24.79 45.11,24.79 J18.3
IOEXPAND1_D2: length 16
  TOP w0.121: U40.6 v1(56.77,29.38) 56.32,29.82 49.19,29.82 46.69,27.33 45.11,27.33 J18.5
IOEXPAND1_D3: length 15.4
  TOP w0.121: U40.7 v1(57.41,27.07)
  LY6 w0.121: J18.7 44.7,27.51 56.97,27.51 v1(57.41,27.07)
IOEXPAND1_D4: length 52
  TOP w0.121: U40.9 v1(58.07,32.67) ; R113.2 19.47,16.89 Q5.G v1(20.79,17.39)
  LY6 w0.121: v1(20.79,17.39) 23.34,19.93 23.34,25.88 29.69,32.23 42.39,32.23 J18.11 45.06,32.23 57.62,32.23 v1(58.07,32.67)
IOEXPAND1_D5: length 60.1
  TOP w0.121: U40.10 v1(57.41,34.98) 56.97,35.42 48.3,35.42 47.84,34.96 45.63,34.96 45.37,35.22 44.61,35.22 J18.13 ; v1(16.37,17.39) Q6.G 15.02,16.89 R117.2
  LY6 w0.121: J18.13 23.73,36.11 17.38,29.76 17.38,18.39 v1(16.37,17.39)
IOEXPAND1_D6: length 66.3
  TOP w0.121: v1(11.92,17.39) Q7.G 10.58,16.89 R118.2 ; U40.11 v1(56.77,32.67)
  LY6 w0.121: v1(11.92,17.39) 14.42,19.88 14.42,30.7 20.77,37.05 42.13,37.05 J18.15 45.32,37.05 47.28,37.05 50.2,34.13 55.3,34.13 v1(56.77,32.67)
IOEXPAND1_D7: length 75.5
  TOP w0.121: R119.2 5.5,16.89 Q8.G v1(6.84,17.39) ; U40.12 v1(56.12,34.98)
  LY6 w0.121: v1(6.84,17.39) 6.84,17.83 7.29,18.27 7.29,33.24 13.64,39.59 42.13,39.59 J18.17 44.92,39.99 44.92,38.62 45.87,37.67 53.76,37.67 54.2,37.23 54.2,36.89 v1(56.12,34.98)
IOEXPAND1_INTN: length 73.2
  TOP w0.121: v2(91.33,63.13) U43.R3 ; U40.13 v1(55.47,32.67)
  LY3 w0.102: v2(91.33,63.13) 90.89,63.13 90.29,62.52 88.81,62.52
  LY3 w0.121: 88.81,62.52 86.43,62.52 84.71,60.8 v1(84.71,48.9)
  BOTTOM w0.121: v1(84.71,48.9) 84.71,44.14 89.42,39.43 89.42,36.87 87.77,35.22 73.44,35.22 73.19,35.47 69,35.47 65.13,31.61 56.53,31.61 v1(55.47,32.67) 55.03,33.11 R101.1
KEYPAD_PWRA: length 107.7
  TOP w0.121: SW2.1 SW2.2 SW1.1 SW1.2 v1(32.2,45.16) 32.3,45.25 32.3,48.81 42.84,59.35 44.87,59.35 45.38,58.84 46.77,58.84 46.9,58.97 86.52,58.97 v1(87.41,59.85) ; SW3.1 SW3.2 v1(20.77,45.16) ; v2(91.33,61.12) U43.U3
  LY6 w0.121: v1(20.77,45.16) v1(32.2,45.16)
  BOTTOM w0.102: v2(91.33,61.12) 91.33,61.11 90.84,60.62 88.81,60.62
  BOTTOM w0.121: v1(87.41,59.85) 87.41,60.24 87.85,60.68 88.75,60.68 88.81,60.62
KEYPAD_PWRB: length 133.6
  TOP w0.121: v2(92.34,61.12) U43.U4 ; v1(9.98,46.47) SW5.2 SW5.1 SW6.2 9.98,28.71 10.58,28.1 16.17,28.1 16.55,27.72 16.55,26.45 17.39,25.61 SW4.1 SW4.2
  LY3 w0.102: 91.99,59.6 91.99,60.62 92.34,60.97 v2(92.34,61.12)
  LY3 w0.121: v1(90.58,46.97) 91.03,47.42 91.03,49.89 89.95,50.96 89.95,57.34 91.99,59.38 91.99,59.6
  LY6 w0.121: v1(9.98,46.47) 90.07,46.47 v1(90.58,46.97)
KEYPAD_SCN0: length 109.4
  TOP w0.121: SW1.3 v1(36.2,40.53) SW1.4 ; v2(96.34,62.12) U43.T8 ; C125.1 v1(27.85,31.11) R121.2 26.83,31.79 26.41,31.36 SW4.4 SW4.3
  LY3 w0.102: v1(94.34,60.04) 94.34,59.92
  LY3 w0.121: 94.34,59.92 94.02,59.6 94.02,45.25 v1(93.89,45.12) ; v1(36.2,40.53) 34.2,40.53 27.85,34.18 v1(27.85,31.11)
  LY6 w0.121: v1(93.89,45.12) 93.89,45.16 93.41,45.64 59.99,45.64 58.46,44.11 54.39,44.11 52.92,42.64 38.3,42.64 v1(36.2,40.53)
  BOTTOM w0.102: v1(94.34,60.04) 94.34,60.47 94.73,60.87 94.73,61.12 95.13,61.52 95.73,61.52 v2(96.34,62.12)
KEYPAD_SCN1: length 130.3
  TOP w0.121: v1(13.98,35.42) SW5.3 SW5.4 ; C126.1 R122.2 38.39,31.79 37.96,31.36 SW2.4 ; SW2.4 SW2.3 ; SW2.4 36.2,33.71 v1(37.9,35.42) 37.9,41.08 42.96,46.14 95.16,46.14 v1(95.26,46.04) ; v2(97.34,62.12) U43.T9
  LY3 w0.102: 95.92,59.6 97.34,61.01 v2(97.34,62.12)
  LY3 w0.121: 95.92,59.6 94.91,58.58 94.91,46.39 v1(95.26,46.04)
  BOTTOM w0.121: v1(13.98,35.42) v1(37.9,35.42)
KEYPAD_SCN2: length 102
  TOP w0.102: 88.81,60.93 89.5,61.62 U43.U1
  TOP w0.121: 88.81,60.93 88.56,60.68 87.61,60.68 87.23,60.3 86.28,59.35 46.77,59.35 46.52,59.09 45.5,59.09 45,59.6 42.33,59.6 32.17,49.44 27.6,49.44 24.77,46.61 SW3.4 SW3.3 24.77,35.09 24.47,34.79 18.24,34.79 18.16,34.71 14.9,34.71 13.98,33.79 SW6.4 15.2,31.36 16.29,30.26 C127.1 R123.2
LCD_DATA0: length 182.8
  TOP w0.121: v2(99.34,61.12) U43.U10 ; v1(120.95,91.72) U2.47
  LY3 w0.121: v1(120.95,91.72) 121.25,91.43 121.25,87.84 120.05,86.65 120.05,69.13 120.31,68.87 v1(120.31,68.24)
  LY6 w0.102: 108,68.38 108.3,68.08 108.39,68.08 ; 107.86,68.52 107.8,68.59 103.08,68.59 102.73,68.23 102.73,67.96 102.49,67.73 101.09,67.73 100.88,67.52 100.17,67.52 99.94,67.29 99.94,66.58 99.74,66.37 99.74,61.97 99.34,61.57 v2(99.34,61.12) 99.34,61.11 98.59,60.36 98.59,60.24 97.95,59.6 88.81,59.6
  LY6 w0.121: v1(120.31,68.24) 116.5,68.24 115.99,67.73 108.75,67.73 108.39,68.08 ; v1(31.28,61.38) 26.2,61.38 26.07,61.25 26.07,60.36 26.2,60.24 31.91,60.24 32.04,60.36 32.04,61.57 32.17,61.7 32.93,61.7 33.06,61.57 33.06,61.25 33.18,61.12 33.44,61.12 33.57,61.25 33.57,61.57 33.69,61.7 34.18,61.7 34.31,61.57 34.31,61.25 34.43,61.12 34.78,61.12 34.91,61.25 34.91,61.57 35.04,61.7 35.27,61.7 35.39,61.58 35.39,61.25 35.52,61.12 35.75,61.12 35.87,61.25 35.87,61.58 36,61.7 36.24,61.7 36.36,61.58 36.36,61.5 36.48,61.38 36.72,61.38 36.84,61.5 36.84,61.58 36.96,61.7 37.2,61.7 37.32,61.58 37.32,60.62 37.45,60.49 37.68,60.49 37.81,60.62 37.81,61.58 37.93,61.7 38.17,61.7 38.29,61.58 38.29,60.62 38.41,60.49 38.64,60.49 38.77,60.62 38.77,61.58 38.89,61.7 39.13,61.7 39.25,61.58 39.25,60.62 39.38,60.49 39.61,60.49 39.74,60.62 39.74,61.58 39.86,61.7 40.1,61.7 40.22,61.58 40.22,60.62 40.35,60.49 40.57,60.49 40.7,60.62 40.7,61.58 40.82,61.7 41.06,61.7 41.18,61.58 41.18,60.62 41.31,60.49 41.54,60.49 41.67,60.62 41.67,61.58 41.79,61.7 42.03,61.7 42.15,61.58 42.15,60.62 42.28,60.49 43.02,60.49 43.15,60.62 43.15,61.57 43.28,61.69 50.14,61.69 50.46,61.38 74.46,61.38 74.71,61.63 75.09,61.63 75.35,61.38 75.76,61.38 76.01,61.63 76.49,61.63 76.75,61.38 77.34,61.38 77.46,61.5 77.46,61.63 77.59,61.76 77.82,61.76 77.94,61.63 77.94,61.5 78.06,61.38 78.3,61.38 78.43,61.5 78.43,62.15 78.55,62.27 78.79,62.27 78.91,62.15 78.91,61.5 79.03,61.38 79.27,61.38 79.39,61.5 79.39,62.15 79.51,62.27 79.75,62.27 79.87,62.15 79.87,61.5 79.99,61.38 86.41,61.38 87.49,60.3 87.6,60.3 87.85,60.04 87.87,60.04 88.3,59.6 88.81,59.6 ; 108,68.38 107.86,68.52
  BOTTOM w0.102: 32.04,85.25 J5.4
  BOTTOM w0.121: v1(31.28,61.38) 31.28,62.51 30.57,63.22 30.57,63.22 30.14,63.65 30.14,67.73 30.7,68.3 30.7,85.13 30.83,85.25 32.04,85.25
LCD_DATA1: length 178.9
  TOP w0.121: U2.46 v1(120.55,89.06) ; v2(100.34,61.12) U43.U11
  LY3 w0.121: v1(120.55,89.06) 120.55,88.42 119.8,87.67 119.8,67.47 v1(120.05,67.22)
  LY6 w0.102: 99.86,59.6 99.94,59.68 99.94,60.66 100.34,61.06 v2(100.34,61.12) 100.34,61.57 100.73,61.96 100.73,61.99 100.75,62.01 100.75,62.87 100.74,62.88 100.74,66.37 101.09,66.72 102.49,66.72 102.73,66.96 102.73,67.09 103.16,67.52 107.76,67.52 107.81,67.47 107.86,67.47
  LY6 w0.121: 99.86,59.6 99.86,59.35 99.35,58.84 73.95,58.84 73.24,59.55 73.24,59.93 72.55,60.62 46.52,60.62 46.32,60.42 45.38,60.42 45.25,60.54 45.25,60.74 45.12,60.87 44.1,60.87 43.88,60.65 43.88,59.47 43.5,59.09 43.08,59.09 42.96,59.22 42.96,60.05 42.83,60.17 32.55,60.17 32.42,60.3 32.42,60.74 32.55,60.87 v1(36.61,60.87) ; 107.86,67.47 108.37,66.97 116.28,66.97 116.47,66.78 116.83,66.78 117.78,67.73 119.54,67.73 v1(120.05,67.22)
  BOTTOM w0.102: 34.91,85.25 J5.3
  BOTTOM w0.121: v1(36.61,60.87) 41.44,60.87 41.57,61 41.57,61.89 41.44,62.01 36.93,62.01 36.81,62.14 36.81,70.24 37.08,70.51 39.66,70.51 39.79,70.64 39.79,71.6 39.66,71.73 39.22,71.73 38.97,71.99 38.97,72.36 39.22,72.61 42.84,72.61 42.96,72.74 42.96,73.95 42.84,74.08 39.34,74.08 39.21,73.95 39.21,73.77 38.95,73.51 38.59,73.51 38.33,73.77 38.33,73.95 38.2,74.08 36.24,74.08 36.11,74.21 36.11,85.13 35.98,85.25 34.91,85.25
LCD_DATA2: length 175.7
  TOP w0.121: v2(101.34,61.12) U43.U12 ; U2.44 119.75,89.24 v1(119.93,89.06)
  LY3 w0.121: v1(119.29,66.59) 119.29,67.6 119.54,67.86 119.54,88.05 119.93,88.43 v1(119.93,89.06)
  LY6 w0.102: 100.88,58.84 100.93,58.89 100.93,60.51 100.95,60.53 100.95,60.82 101.26,61.12 v2(101.34,61.12) 101.34,61.46 101.76,61.89 101.76,62.65 101.94,62.83 101.94,63.29 102.17,63.52 102.6,63.52 102.94,63.86 102.94,64.29 103.17,64.52 103.6,64.52 103.94,64.86 103.94,65.29 104.17,65.52 104.88,65.52 105.09,65.72 107.83,65.72 107.86,65.7
  LY6 w0.121: 107.86,65.7 115.24,65.7 116.06,64.87 117.58,64.87 v1(119.29,66.59) ; 100.88,58.84 100.11,58.08 72.85,58.08 72.3,57.52 64.93,57.52 63.52,58.93 60.27,58.93 59.35,59.85 47,59.85 46.84,59.7 46.84,58.97 46.58,58.7 45.13,58.7 44.61,59.23 43.98,59.23 43.85,59.1 43.85,58.46 43.47,58.08 42.84,58.08 42.71,58.2 42.71,59.73 42.58,59.85 29.76,59.85 29.63,59.73 29.63,59.22 29.76,59.09 v1(31.28,59.09)
  BOTTOM w0.102: J5.6 32.17,83.98
  BOTTOM w0.121: v1(31.28,59.09) 31.03,59.09 30.9,58.97 30.9,56.79 31.72,55.96 31.72,50.08 31.85,49.95 32.17,49.95 32.3,50.08 32.3,56.17 31.41,57.06 31.41,58.2 31.79,58.58 31.79,62.35 30.68,63.46 30.67,63.46 30.39,63.74 30.39,67.47 30.95,68.04 30.95,83.86 31.08,83.98 32.17,83.98
LCD_DATA3: length 178.3
  TOP w0.121: v1(119.06,91.99) 119.35,91.7 U2.43 ; v2(102.33,61.12) U43.U13
  LY3 w0.121: v1(119.06,91.99) 119.29,91.76 119.29,89.57 119.48,89.38 119.48,88.76 118.96,88.24 118.79,88.24 118.43,87.87 118.43,65.59 118.02,65.19 v1(118.02,64.43)
  LY6 w0.102: 107.86,64.45 107.79,64.52 105.79,64.52 105.58,64.72 105.07,64.72 104.86,64.52 104.17,64.52 103.94,64.29 103.94,63.86 103.6,63.52 103.17,63.52 102.94,63.29 102.94,62.39 102.73,62.18 102.73,61.96 102.33,61.57 v2(102.33,61.12) 102.33,61.06 101.94,60.67 101.94,59.65 101.89,59.6
  LY6 w0.121: v1(118.02,64.43) 117.13,64.43 116.62,63.92 115.1,63.92 114.57,64.45 107.86,64.45 ; 101.89,59.6 101.89,58.58 100.64,57.33 83.26,57.33 82.99,57.06 82.99,57.06 82.71,56.78 64.62,56.78 63.21,58.19 59.24,58.19 58.33,59.09 56.32,59.09 55.13,57.89 54.73,57.89 54.61,58.01 54.61,58.98 54.49,59.1 54.25,59.1 54.13,58.98 54.13,58.01 54.01,57.89 53.77,57.89 53.64,58.01 53.64,58.98 53.52,59.1 53.28,59.1 53.16,58.98 53.16,58.2 53.04,58.08 52.81,58.08 52.68,58.2 52.68,58.98 52.56,59.1 52.2,59.1 52.2,59.09 48.68,59.09 47.48,57.89 44.18,57.89 43.73,57.44 41.5,57.44 40.45,58.49 36.9,58.49 v1(36.36,57.95)
  BOTTOM w0.102: J5.5 34.91,83.98
  BOTTOM w0.121: 34.91,83.98 35.74,83.98 35.86,83.86 35.86,74.1 36.14,73.83 37.96,73.83 38.08,73.7 38.08,73.67 38.49,73.26 39.03,73.26 39.15,73.14 39.15,72.89 39.03,72.77 38.85,72.77 38.72,72.64 38.72,72.46 38.72,71.58 38.85,71.45 39.41,71.45 39.53,71.33 39.53,70.89 39.41,70.76 36.8,70.76 36.56,70.52 36.56,70.34 36.56,70.14 36.56,70.14 36.56,62.24 36.56,62.24 36.56,62.04 36.56,62.04 36.83,61.77 39.28,61.77 39.41,61.64 39.41,61.51 39.28,61.38 36.23,61.38 36.17,61.32 36.17,60.42 36.23,60.36 42.2,60.36 42.33,60.24 42.33,58.97 42.2,58.84 36.49,58.84 36.36,58.71 v1(36.36,57.95)
LCD_DATA4: length 176.9
  TOP w0.121: v2(103.33,61.12) U43.U14 ; v1(118.35,91.73) 118.55,91.53 U2.41
  LY3 w0.121: v1(118.35,91.73) 118.55,91.53 118.55,89.29 118.59,89.25 118.59,88.39 118.04,87.84 118.04,65.56 117.58,65.1 117.58,63.72 v1(118.02,63.28)
  LY6 w0.102: 102.93,59.6 102.93,60.64 103.33,61.04 v2(103.33,61.12) 103.33,61.57 103.73,61.96 103.73,62.36 103.94,62.58 103.94,63.29 104.17,63.52 104.86,63.52 105.07,63.72 105.18,63.72 105.19,63.73 105.63,63.73 105.85,63.52 107.75,63.52 107.86,63.41
  LY6 w0.121: v1(32.3,57.06) 32.68,56.68 37.92,56.68 38.99,57.75 39.57,57.75 41.14,56.17 44.51,56.17 45.49,57.15 55.43,57.15 56.61,58.32 57.74,58.32 57.81,58.24 58.62,57.44 62.9,57.44 64.31,56.04 100.49,56.04 102.93,58.48 102.93,59.6 ; v1(118.02,63.28) 117.71,62.97 115.15,62.97 114.46,63.66 109.28,63.66 109.03,63.41 107.86,63.41
  BOTTOM w0.121: v1(32.3,57.06) 31.79,57.06 31.66,57.19 31.66,58.11 31.88,58.33 31.92,58.33 32.05,58.46 32.05,62.01 32.17,62.14 34.21,62.14 34.33,62.27 34.33,62.66 34.21,62.79 31.7,62.79 30.78,63.71 30.77,63.71 30.64,63.84 30.64,66.71 30.77,66.84 32.55,66.84 32.68,66.71 32.68,66.08 32.8,65.95 33.44,65.95 33.57,66.08 33.57,67.98 33.44,68.11 31.33,68.11 31.2,68.24 31.2,70.01 31.33,70.14 32.42,70.14 32.55,70.01 32.55,68.74 32.68,68.62 33.44,68.62 33.57,68.74 33.57,70.01 33.69,70.14 33.84,70.14 33.97,70.27 33.97,71.03 33.84,71.16 31.33,71.16 31.2,71.28 31.2,72.3 31.33,72.43 32.8,72.43 32.93,72.55 32.93,72.94 32.8,73.06 31.33,73.06 31.2,73.19 31.2,82.51 31.41,82.71 J5.8
LCD_DATA5: length 173.9
  TOP w0.121: U2.40 118.15,88.64 v1(118.05,88.53) ; v2(104.33,61.12) U43.U15
  LY3 w0.121: v1(118.05,88.53) 118.05,88.19 117.8,87.95 117.8,87.93 117.8,65.67 117.33,65.2 117.33,63.21 118.02,62.52 v1(118.02,61.89)
  LY6 w0.102: 107.86,61.72 106.12,61.72 105.73,62.11 105.73,62.29 105.5,62.52 105.17,62.52 104.77,62.12 104.77,61.76 104.33,61.32 v2(104.33,61.12) 104.14,60.93 104.14,60.76 103.93,60.56 103.93,59.61 103.92,59.6
  LY6 w0.121: v1(118.02,61.89) 117.31,61.89 117.28,61.91 115.12,61.91 115.02,61.82 113.83,61.82 113.73,61.72 110.55,61.72 109.82,62.45 109.46,62.45 108.72,61.72 107.86,61.72 ; 103.92,59.6 103.92,58.33 99.53,53.94 99.31,53.94 98.74,53.37 65.83,53.37 62.5,56.7 58.31,56.7 57.44,57.57 56.93,57.57 55.77,56.41 45.9,56.41 45.41,55.92 45.41,55.92 44.89,55.4 40.59,55.4 39.76,56.23 38.9,56.23 37.9,55.23 36.29,55.23 36.23,55.28 v1(35.85,55.28)
  BOTTOM w0.102: 34.91,81.88 J5.7
  BOTTOM w0.121: 34.91,81.88 35.62,81.17 35.62,72.46 35.78,72.3 36.74,72.3 36.87,72.43 36.87,73.32 36.99,73.44 37.96,73.44 38.47,72.93 38.47,72.56 38.47,72.56 38.47,72.15 38.47,71.13 38.34,71.01 36.69,71.01 36.31,70.62 36.31,70.45 36.31,61.76 36.18,61.63 36.05,61.63 35.92,61.51 35.92,60.11 36.05,59.98 41.95,59.98 42.07,59.85 42.07,59.21 41.95,59.09 36.05,59.09 35.92,58.96 35.92,58.14 35.92,58.13 35.92,57.57 36.04,57.44 36.11,57.44 36.23,57.31 36.23,55.8 36.56,55.48 36.68,55.48 36.8,55.36 36.8,53.5 36.67,53.38 35.98,53.38 35.85,53.5 v1(35.85,55.28)
LCD_DATA6: length 170.5
  TOP w0.121: v2(105.34,61.12) U43.U16 ; v1(117.54,89.06) 117.51,89.09 117.51,89.16 117.35,89.32 U2.38
  LY3 w0.121: v1(116.75,61.47) 117.08,61.81 117.08,65.3 117.28,65.5 117.54,65.76 v1(117.54,89.06)
  LY6 w0.102: 105.58,59.6 105.58,59.81 105.73,59.96 105.73,60.29 105.34,60.68 v2(105.34,61.12) 105.41,61.12 106.01,60.53 107.86,60.53
  LY6 w0.121: 107.86,60.53 108.2,60.53 108.24,60.49 114.97,60.49 115.23,60.74 116.02,60.74 v1(116.75,61.47) ; v1(45.38,54.9) 46.01,54.9 46.46,55.35 46.84,55.35 47.54,54.65 56.04,54.65 57.31,55.92 61.38,55.92 64.94,52.35 102.52,52.35 104.87,54.7 104.87,58.89 105.58,59.6
  BOTTOM w0.102: 39.36,77.63 J6.15
  BOTTOM w0.121: 39.36,77.63 40.68,77.63 40.8,77.76 40.8,78.02 40.68,78.14 39.92,78.14 39.79,78.27 39.79,78.65 39.92,78.78 40.55,78.78 40.68,78.9 40.68,80.83 40.8,80.96 48.66,80.96 48.94,80.68 48.94,55.03 48.68,54.77 48.17,54.77 47.91,55.03 47.91,61.5 47.78,61.63 45.27,61.63 45,61.35 45,59.6 45.38,59.22 v1(45.38,54.9)
LCD_DATA7: length 169.9
  TOP w0.121: v2(107.34,61.12) U43.U18 ; v1(116.88,91.68) 116.95,91.61 U2.37
  LY3 w0.121: v1(116.88,91.68) 116.88,91.19 117.1,90.97 117.1,86.55 117.26,86.39 117.26,66.04 116.84,65.62 116.84,62.76 v1(115.55,61.47)
  LY6 w0.102: 107.86,60.94 107.52,60.94 v2(107.34,61.12) 107.34,61.11 106.96,60.73 106.17,60.73 105.73,61.17 105.73,61.29 105.5,61.52 105.17,61.52 104.94,61.29 104.94,60.02 104.94,60.01 104.94,59.96 104.62,59.64 104.62,59.6
  LY6 w0.121: 104.62,59.6 104.62,55.98 101.24,52.6 65.2,52.6 61.6,56.2 57.09,56.2 56.04,55.16 47.54,55.16 47.03,55.66 v1(46.14,55.66) ; v1(115.55,61.47) 115.02,60.94 107.86,60.94
  BOTTOM w0.102: J6.9 39.36,81.44
  BOTTOM w0.121: 39.36,81.44 39.41,81.44 39.53,81.57 39.53,82.08 39.66,82.21 40.82,82.21 40.95,82.33 40.95,83.48 41.07,83.6 41.31,83.6 41.43,83.48 41.43,81.82 41.55,81.7 41.79,81.7 41.92,81.82 41.92,83.48 42.04,83.6 42.28,83.6 42.4,83.48 42.4,81.82 42.52,81.7 47.92,81.7 48.04,81.83 48.04,82.09 48.17,82.21 48.69,82.21 48.82,82.33 48.82,82.39 49.02,82.59 49.57,82.59 49.69,82.46 49.69,54.14 49.57,54.01 47.28,54.01 47.15,54.14 47.15,58.2 47.03,58.33 46.14,58.33 46.01,58.2 46.01,56.93 46.14,56.81 v1(46.14,55.66)
LCD_DATA8: length 174.7
  TOP w0.121: v1(116.63,89.04) 116.63,89.18 116.55,89.26 U2.36 ; v2(100.34,62.12) U43.T11
  LY3 w0.121: v1(116.65,67.22) 117,67.58 117,86.29 116.66,86.64 116.66,88.4 116.63,88.43 v1(116.63,89.04)
  LY6 w0.102: 107.86,67.73 102.86,67.73 102.65,67.52 101.17,67.52 100.94,67.29 100.94,67.16 100.3,66.52 100.17,66.52 99.94,66.29 99.94,62.96 100.34,62.57 v2(100.34,62.12) 100.34,62.11 99.86,61.63 99.86,60.87 99.73,60.74 99.73,59.85 99.48,59.6
  LY6 w0.121: v1(116.65,67.22) 115.69,67.22 115.56,67.35 108.56,67.35 108.18,67.73 107.86,67.73 ; 99.48,59.6 99.35,59.47 99.35,59.35 99.1,59.09 79.79,59.09 79.67,59.22 79.67,60.24 79.54,60.36 79.3,60.36 79.17,60.24 79.17,59.21 79.05,59.09 78.81,59.09 78.69,59.21 78.69,60.75 78.57,60.87 78.33,60.87 78.21,60.75 78.21,59.21 78.08,59.09 77.84,59.09 77.72,59.21 77.72,60.75 77.6,60.87 77.36,60.87 77.24,60.75 77.24,59.21 77.12,59.09 76.88,59.09 76.76,59.21 76.76,60.75 76.64,60.87 76.4,60.87 76.28,60.75 76.28,59.21 76.15,59.09 75.91,59.09 75.79,59.21 75.79,60.75 75.67,60.87 75.43,60.87 75.31,60.75 75.31,59.21 75.19,59.09 74.95,59.09 74.83,59.21 74.83,60.75 74.71,60.87 74.47,60.87 74.34,60.75 74.34,59.47 74.22,59.35 73.99,59.35 73.86,59.47 73.86,60.75 73.74,60.87 v1(45.88,60.87)
  BOTTOM w0.102: 39.36,80.17 J6.11
  BOTTOM w0.121: v1(45.88,60.87) 45.88,60.1 46.07,59.91 46.07,59.54 45.88,59.36 45.88,58.71 46.01,58.58 47.28,58.58 47.41,58.46 47.41,54.39 47.54,54.27 49.31,54.27 49.44,54.39 49.44,82.21 49.31,82.33 49.17,82.33 48.8,81.96 48.74,81.96 48.42,81.96 48.3,81.84 48.3,81.58 48.17,81.45 41.19,81.45 41.06,81.58 41.06,81.83 40.93,81.95 39.92,81.95 39.79,81.83 39.79,81.06 39.92,80.94 40.04,80.94 40.17,80.81 40.17,80.3 40.04,80.17 39.36,80.17
LCD_DATA9: length 177.6
  TOP w0.121: v1(116.12,91.71) 116.15,91.67 U2.35 ; v2(101.34,62.12) U43.T12
  LY3 w0.121: v1(116.12,91.71) 116.15,91.67 116.15,89.29 116.19,89.25 116.19,86.75 116.75,86.19 116.75,68.11 116.19,67.55 116.19,65.37 v1(116.24,65.32)
  LY6 w0.102: 107.86,66.33 107.73,66.33 107.55,66.52 101.17,66.52 100.94,66.29 100.94,62.96 101.34,62.57 v2(101.34,62.12) 101.34,62.09 100.73,61.49 100.73,59.71 100.62,59.6
  LY6 w0.121: 100.62,59.6 100.62,58.97 99.99,58.33 68.49,58.33 67.93,57.77 67.6,57.77 67.44,57.94 67.44,59.85 67.18,60.11 66.82,60.11 66.7,59.99 66.7,58.58 66.58,58.46 66.35,58.46 66.22,58.58 66.22,59.99 66.1,60.11 65.86,60.11 65.74,59.99 65.74,58.71 65.61,58.58 65.38,58.58 65.26,58.71 65.26,59.99 65.14,60.11 64.89,60.11 64.77,59.99 64.77,59.3 64.65,59.18 64.41,59.18 64.29,59.3 64.29,59.99 64.17,60.11 63.93,60.11 63.81,59.99 63.81,59.3 63.69,59.18 63.45,59.18 63.33,59.3 63.33,59.99 63.2,60.11 62.96,60.11 62.84,59.99 62.84,59.3 62.72,59.18 62.48,59.18 62.36,59.3 62.36,59.99 62.24,60.11 62,60.11 61.88,59.99 61.88,59.3 61.76,59.18 61.52,59.18 61.4,59.3 61.4,59.99 61.27,60.11 61.03,60.11 60.91,59.99 60.91,59.3 60.79,59.18 60.55,59.18 60.43,59.3 60.43,59.99 60.31,60.11 46.9,60.11 46.52,59.73 v1(45.63,59.73) ; v1(116.24,65.32) 115.23,66.33 107.86,66.33
  BOTTOM w0.102: 39.36,78.9 J6.13
  BOTTOM w0.121: v1(45.63,59.73) 45.38,59.73 45.25,59.85 45.25,61.25 45.38,61.38 46.39,61.38 46.51,61.25 46.51,60.13 46.64,60.01 47.54,60.01 47.66,59.89 47.66,59.65 47.54,59.52 46.51,59.52 46.39,59.4 46.39,59.16 46.51,59.04 47.54,59.04 47.66,58.92 47.66,54.65 47.79,54.52 49.06,54.52 49.19,54.65 49.19,81.08 49.06,81.2 40.69,81.2 40.42,80.93 40.42,80.2 40.3,80.08 40.3,79.51 39.69,78.9 39.36,78.9
LCD_DATA10: length 174.2
  TOP w0.121: U2.33 v1(115.35,91.73) ; v2(102.33,62.12) U43.T13
  LY3 w0.121: v1(115.48,64.43) 115.48,81.32 115.21,81.58 115.21,88.55 115.22,88.56 115.22,89.32 115.35,89.45 v1(115.35,91.73)
  LY6 w0.102: 107.86,64.93 107.65,64.72 106.08,64.72 105.73,65.08 105.73,65.29 105.5,65.52 105.17,65.52 104.94,65.29 104.94,64.94 104.73,64.72 104.09,64.72 103.74,64.37 103.74,63.95 103.51,63.72 103.09,63.72 102.74,63.37 102.74,62.9 102.4,62.57 102.33,62.57 v2(102.33,62.12) 102.33,62.08 101.74,61.48 101.74,59.83 101.64,59.73 101.64,59.6
  LY6 w0.121: 107.86,64.93 114.97,64.93 v1(115.48,64.43) ; 101.64,59.6 101.64,58.71 100.5,57.58 83.15,57.58 82.6,57.03 64.72,57.03 63.31,58.43 59.35,58.43 59.22,58.56 59.22,58.97 58.84,59.34 56.22,59.34 55.32,58.43 55.05,58.43 54.86,58.63 54.86,59.08 54.59,59.35 48.58,59.35 47.38,58.14 44.04,58.14 43.73,57.82 42.58,57.82 42.46,57.95 42.46,59.47 42.33,59.6 32.42,59.6 32.3,59.47 v1(32.3,57.7)
  BOTTOM w0.102: J5.10 32.17,81.44
  BOTTOM w0.121: v1(32.3,57.7) 32.3,58.97 32.42,59.09 34.45,59.09 34.58,59.22 34.58,59.6 34.45,59.73 32.42,59.73 32.3,59.85 32.3,60.74 32.42,60.87 34.45,60.87 34.58,61 34.58,61.25 34.45,61.38 32.93,61.38 32.8,61.51 32.8,61.76 32.93,61.89 34.45,61.89 34.58,62.01 34.58,62.91 34.45,63.04 31.8,63.04 30.9,63.94 30.9,65.57 31.03,65.7 33.69,65.7 33.82,65.82 33.82,69 34.59,69.77 34.59,70.7 34.21,71.08 34.21,71.28 34.09,71.41 31.66,71.41 31.53,71.54 31.53,72.05 31.66,72.17 34.09,72.17 34.21,72.3 34.21,72.81 34.09,72.94 33.44,72.94 33.32,73.06 33.32,73.57 33.19,73.7 31.57,73.7 31.45,73.82 31.45,81.01 31.88,81.44 32.17,81.44
LCD_DATA11: length 171
  TOP w0.121: U2.32 114.95,89.17 114.76,88.98 v1(114.76,88.94) ; v2(103.33,62.12) U43.T14
  LY3 w0.121: v1(114.76,88.94) 114.76,88.26 114.97,88.05 114.97,81.37 115.23,81.1 115.23,65.38 115.04,65.19 115.04,63.85 v1(115.48,63.41)
  LY6 w0.102: 107.86,63.92 107.66,63.72 106.15,63.72 105.73,64.14 105.73,64.29 105.5,64.52 105.17,64.52 104.94,64.29 104.94,64.17 104.5,63.73 104.1,63.73 103.74,63.37 103.74,62.97 103.34,62.57 103.33,62.57 v2(103.33,62.12) 103.33,62.09 102.91,61.67 102.91,61.12 102.65,60.87 102.65,60.36 102.73,60.29 102.73,59.96 102.65,59.89 102.65,59.6
  LY6 w0.121: 107.86,63.92 114.55,63.92 115.06,63.41 v1(115.48,63.41) ; 102.65,59.6 102.65,58.58 100.35,56.29 64.41,56.29 63.01,57.69 58.84,57.69 57.95,58.58 56.52,58.58 55.33,57.4 51.25,57.4 51.13,57.52 51.13,58.34 51.01,58.46 50.77,58.46 50.65,58.34 50.65,57.52 50.53,57.4 50.29,57.4 50.17,57.52 50.17,58.34 50.05,58.46 49.8,58.46 49.68,58.34 49.68,57.52 49.56,57.4 49.32,57.4 49.2,57.52 49.2,58.34 49.08,58.46 48.84,58.46 48.72,58.34 48.72,57.52 48.6,57.4 45.38,57.4 45.36,57.38 45.31,57.38 44.36,56.43 41.31,56.43 39.74,58 38.69,58 37.88,57.19 v1(33.92,57.19)
  BOTTOM w0.102: 32.04,77.38 32.3,77.63 J5.16
  BOTTOM w0.121: v1(33.92,57.19) 33.82,57.09 33.82,46.9 33.69,46.77 33.44,46.77 33.31,46.9 33.31,57.57 33.44,57.7 34.33,57.7 34.46,57.82 34.46,58.18 35.16,58.88 35.16,70.5 35.16,70.97 34.97,71.16 34.84,71.16 34.71,71.28 34.71,74.21 34.58,74.33 32.07,74.33 31.94,74.46 31.94,77.28 32.04,77.38
